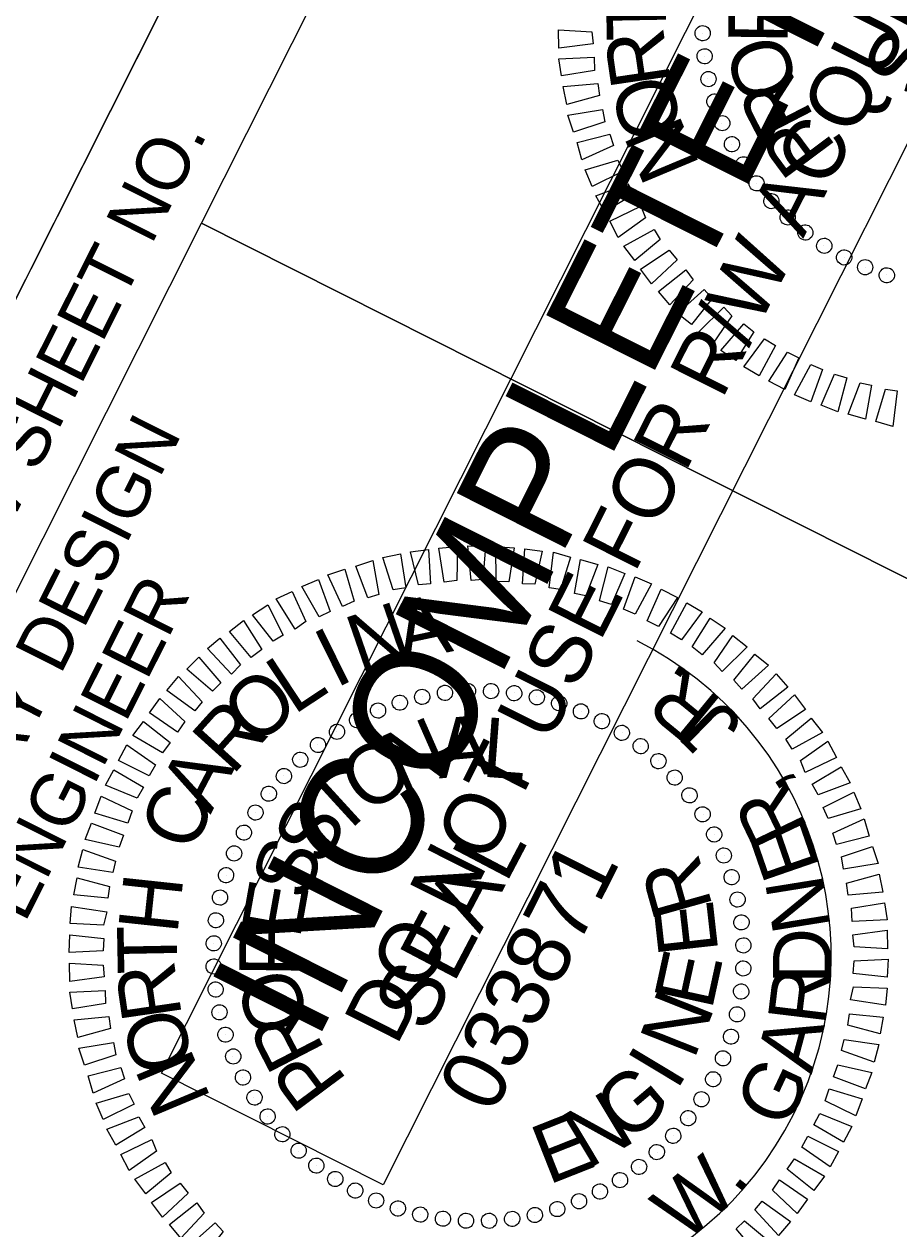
# Model space of a CAD drawing. Extents: x 2010322 to 2012069, y 441674 to 443687.
# Drawn here: x 2011069.6 to 2011152.3, y 443452.2 to 443566.2 of the extents above; entities that cross this region are included whole.
import ezdxf

# ---------------------------------------------------------------- set-up
doc = ezdxf.new("R2010")
doc.units = 0
for name, color, linetype in [('Scratch_Level_0', 7, 'Continuous'), ('Sheet Plan And Profile CELL', 7, 'Continuous'), ('Sheet Professional Seal CELL', 7, 'Continuous'), ('Sheet Profile Grid Minor CELL', 7, 'Continuous'), ('Sheet Sticker Incomplete CELL', 7, 'Continuous')]:
    doc.layers.add(name, color=color, linetype=linetype)

msp = doc.modelspace()

# ---------------------------------------------------------------- linework, layer by layer
at = {"layer": 'Scratch_Level_0'}
msp.add_arc((2011112.57, 443478.04), 33.36, 243.277, 63.277, dxfattribs=at)
at = {"layer": 'Sheet Plan And Profile CELL'}
for p, q in [((2011030.22, 443463.59), (2011120.17, 443642.28)), ((2011086.37, 443547.34), (2011186.81, 443496.77))]:
    msp.add_line(p, q, dxfattribs=at)
for points in [[(2011007.84, 443474.86), (2011097.8, 443653.54), (2011120.17, 443642.28), (2011030.22, 443463.59)], [(2011086.37, 443547.34), (2011131.34, 443636.65), (2011231.82, 443586.07), (2011186.86, 443496.75)], [(2011041.38, 443457.97), (2011086.37, 443547.34), (2011186.86, 443496.75), (2011141.87, 443407.38)]]:
    msp.add_lwpolyline(points, close=True, dxfattribs=at)
at = {"layer": 'Sheet Professional Seal CELL'}
for p, q in [((2011133.77, 443565.33), (2011133.77, 443565.33)), ((2011133.94, 443563.12), (2011133.94, 443563.12)), ((2011134.27, 443560.99), (2011134.27, 443560.99)), ((2011134.87, 443558.84), (2011134.87, 443558.84)), ((2011135.58, 443556.81), (2011135.58, 443556.81)), ((2011136.53, 443554.81), (2011136.53, 443554.81)), ((2011137.58, 443552.89), (2011137.58, 443552.89)), ((2011138.87, 443551.12), (2011138.87, 443551.12)), ((2011140.25, 443549.41), (2011140.25, 443549.41)), ((2011141.81, 443547.84), (2011141.81, 443547.84)), ((2011143.49, 443546.5), (2011143.49, 443546.5)), ((2011145.25, 443545.22), (2011145.25, 443545.22)), ((2011147.15, 443544.1), (2011147.15, 443544.1)), ((2011149.14, 443543.15), (2011149.14, 443543.15)), ((2011151.19, 443542.45), (2011151.19, 443542.45)), ((2011107.25, 443502.6), (2011107.25, 443502.6)), ((2011109.37, 443502.93), (2011109.37, 443502.93)), ((2011111.59, 443503.11), (2011111.59, 443503.11)), ((2011113.78, 443503.12), (2011113.78, 443503.12)), ((2011115.93, 443502.94), (2011115.93, 443502.94)), ((2011118.07, 443502.53), (2011118.07, 443502.53)), ((2011103.06, 443501.3), (2011103.06, 443501.3)), ((2011105.1, 443502.01), (2011105.1, 443502.01)), ((2011120.22, 443501.9), (2011120.22, 443501.9)), ((2011122.27, 443501.2), (2011122.27, 443501.2)), ((2011101.07, 443500.34), (2011101.07, 443500.34)), ((2011124.26, 443500.25), (2011124.26, 443500.25)), ((2011099.14, 443499.29), (2011099.14, 443499.29)), ((2011126.16, 443499.13), (2011126.16, 443499.13)), ((2011097.37, 443498), (2011097.37, 443498)), ((2011127.92, 443497.85), (2011127.92, 443497.85)), ((2011095.67, 443496.62), (2011095.67, 443496.62)), ((2011129.59, 443496.51), (2011129.59, 443496.51)), ((2011094.1, 443495.06), (2011094.1, 443495.06)), ((2011131.15, 443494.94), (2011131.15, 443494.94)), ((2011092.76, 443493.39), (2011092.76, 443493.39)), ((2011132.54, 443493.23), (2011132.54, 443493.23)), ((2011091.48, 443491.62), (2011091.48, 443491.62)), ((2011133.83, 443491.46), (2011133.83, 443491.46)), ((2011090.35, 443489.73), (2011090.35, 443489.73)), ((2011134.87, 443489.54), (2011134.87, 443489.54)), ((2011089.41, 443487.74), (2011089.41, 443487.74)), ((2011135.83, 443487.54), (2011135.83, 443487.54)), ((2011088.71, 443485.68), (2011088.71, 443485.68)), ((2011136.54, 443485.51), (2011136.54, 443485.51)), ((2011088.08, 443483.54), (2011088.08, 443483.54)), ((2011137.14, 443483.36), (2011137.14, 443483.36)), ((2011087.67, 443481.39), (2011087.67, 443481.39)), ((2011137.47, 443481.23), (2011137.47, 443481.23)), ((2011087.48, 443479.25), (2011087.48, 443479.25)), ((2011137.64, 443479.02), (2011137.64, 443479.02)), ((2011112.57, 443478.04), (2011112.57, 443478.04)), ((2011087.5, 443477.06), (2011087.5, 443477.06)), ((2011137.66, 443476.83), (2011137.66, 443476.83)), ((2011087.67, 443474.84), (2011087.67, 443474.84)), ((2011137.47, 443474.68), (2011137.47, 443474.68)), ((2011088, 443472.72), (2011088, 443472.72)), ((2011137.06, 443472.54), (2011137.06, 443472.54)), ((2011088.6, 443470.57), (2011088.6, 443470.57)), ((2011136.43, 443470.39), (2011136.43, 443470.39)), ((2011089.31, 443468.53), (2011089.31, 443468.53)), ((2011135.73, 443468.34), (2011135.73, 443468.34)), ((2011090.27, 443466.54), (2011090.27, 443466.54)), ((2011134.79, 443466.35), (2011134.79, 443466.35)), ((2011091.31, 443464.61), (2011091.31, 443464.61)), ((2011133.66, 443464.45), (2011133.66, 443464.45)), ((2011092.6, 443462.84), (2011092.6, 443462.84)), ((2011132.38, 443462.69), (2011132.38, 443462.69)), ((2011093.99, 443461.14), (2011093.99, 443461.14)), ((2011131.04, 443461.01), (2011131.04, 443461.01)), ((2011095.55, 443459.57), (2011095.55, 443459.57)), ((2011129.47, 443459.45), (2011129.47, 443459.45)), ((2011097.22, 443458.22), (2011097.22, 443458.22)), ((2011127.76, 443458.07), (2011127.76, 443458.07)), ((2011098.98, 443456.94), (2011098.98, 443456.94)), ((2011125.99, 443456.78), (2011125.99, 443456.78)), ((2011100.88, 443455.82), (2011100.88, 443455.82)), ((2011124.07, 443455.73), (2011124.07, 443455.73)), ((2011102.87, 443454.88), (2011102.87, 443454.88)), ((2011122.08, 443454.78), (2011122.08, 443454.78)), ((2011104.92, 443454.18), (2011104.92, 443454.18)), ((2011107.07, 443453.55), (2011107.07, 443453.55)), ((2011117.89, 443453.47), (2011117.89, 443453.47)), ((2011120.04, 443454.07), (2011120.04, 443454.07)), ((2011109.21, 443453.14), (2011109.21, 443453.14)), ((2011111.36, 443452.95), (2011111.36, 443452.95)), ((2011113.55, 443452.97), (2011113.55, 443452.97)), ((2011115.77, 443453.14), (2011115.77, 443453.14))]:
    msp.add_line(p, q, dxfattribs=at)
for points in [[(2011123.41, 443564.33), (2011120.17, 443563.89), (2011120.15, 443565.64), (2011123.3, 443565.45)], [(2011123.54, 443561.8), (2011120.43, 443561.3), (2011120.17, 443562.89), (2011123.5, 443563.06)], [(2011124.02, 443559.43), (2011120.91, 443558.59), (2011120.58, 443560.27), (2011123.87, 443560.57)], [(2011124.51, 443556.95), (2011121.56, 443555.97), (2011121.02, 443557.58), (2011124.31, 443558.11)], [(2011125.33, 443554.69), (2011122.35, 443553.33), (2011121.89, 443554.97), (2011124.98, 443555.76)], [(2011126.24, 443552.27), (2011123.33, 443550.83), (2011122.66, 443552.39), (2011125.75, 443553.3)], [(2011127.26, 443550.08), (2011124.53, 443548.43), (2011123.66, 443549.93), (2011126.71, 443551.08)], [(2011128.38, 443547.84), (2011125.78, 443546.01), (2011124.98, 443547.53), (2011127.93, 443548.96)], [(2011129.76, 443545.8), (2011127.36, 443543.82), (2011126.31, 443545.18), (2011129.18, 443546.76)], [(2011131.36, 443543.87), (2011128.94, 443541.62), (2011127.89, 443542.99), (2011130.6, 443544.81)], [(2011132.88, 443541.99), (2011130.68, 443539.62), (2011129.59, 443540.9), (2011132.19, 443542.95)], [(2011134.68, 443540.24), (2011132.71, 443537.76), (2011131.39, 443538.82), (2011133.92, 443541.07)], [(2011136.53, 443538.58), (2011134.78, 443535.99), (2011133.42, 443537.07), (2011135.78, 443539.41)], [(2011138.63, 443537.08), (2011136.93, 443534.35), (2011135.5, 443535.3), (2011137.67, 443537.84)], [(2011140.66, 443535.77), (2011139.11, 443532.92), (2011137.68, 443533.75), (2011139.64, 443536.4)], [(2011142.87, 443534.6), (2011141.55, 443531.63), (2011140.03, 443532.4), (2011141.8, 443535.14)], [(2011145.13, 443533.52), (2011144.02, 443530.44), (2011142.46, 443531.12), (2011144.01, 443533.98)], [(2011147.41, 443532.71), (2011146.57, 443529.5), (2011144.99, 443530.13), (2011146.25, 443533.07)], [(2011149.75, 443532.04), (2011149.19, 443528.8), (2011147.53, 443529.29), (2011148.68, 443532.24)], [(2011152.17, 443531.49), (2011151.76, 443528.12), (2011150.15, 443528.59), (2011151.07, 443531.65)], [(2011104.48, 443512.67), (2011103.51, 443515.74), (2011105.18, 443516.07), (2011105.69, 443512.85)], [(2011106.9, 443513.14), (2011106.12, 443516.27), (2011107.85, 443516.47), (2011108.02, 443513.25)], [(2011109.31, 443513.38), (2011108.81, 443516.6), (2011110.57, 443516.77), (2011110.52, 443513.55)], [(2011111.86, 443513.55), (2011111.56, 443516.84), (2011113.24, 443516.72), (2011112.98, 443513.66)], [(2011114.23, 443513.47), (2011114.22, 443516.78), (2011115.94, 443516.65), (2011115.44, 443513.43)], [(2011116.74, 443513.22), (2011116.95, 443516.53), (2011118.58, 443516.32), (2011117.9, 443513.2)], [(2011119.24, 443512.86), (2011119.65, 443516.23), (2011121.26, 443515.76), (2011120.34, 443512.7)], [(2011102.09, 443511.92), (2011100.95, 443514.9), (2011102.57, 443515.43), (2011103.14, 443512.23)], [(2011121.65, 443512.31), (2011122.22, 443515.55), (2011123.87, 443515.06), (2011122.73, 443512.11)], [(2011124, 443511.64), (2011124.84, 443514.85), (2011126.42, 443514.22), (2011125.16, 443511.28)], [(2011099.71, 443511.1), (2011098.31, 443514.1), (2011099.93, 443514.63), (2011100.81, 443511.61)], [(2011126.28, 443510.83), (2011127.38, 443513.91), (2011128.95, 443513.23), (2011127.39, 443510.37)], [(2011097.48, 443510.1), (2011095.85, 443512.99), (2011097.42, 443513.66), (2011098.53, 443510.63)], [(2011128.53, 443509.75), (2011129.86, 443512.72), (2011131.38, 443511.95), (2011129.61, 443509.21)], [(2011095.21, 443508.94), (2011093.41, 443511.81), (2011094.93, 443512.5), (2011096.24, 443509.66)], [(2011130.74, 443508.58), (2011132.29, 443511.43), (2011133.72, 443510.6), (2011131.77, 443507.95)], [(2011093.13, 443507.81), (2011091.19, 443510.3), (2011092.63, 443511.25), (2011094.09, 443508.39)], [(2011091.07, 443506.27), (2011089, 443508.71), (2011090.32, 443509.78), (2011092.06, 443507.01)], [(2011132.78, 443507.27), (2011134.48, 443510), (2011135.91, 443509.05), (2011133.73, 443506.51)], [(2011089.21, 443504.69), (2011086.91, 443507.13), (2011088.08, 443508.11), (2011090.04, 443505.56)], [(2011134.87, 443505.77), (2011136.62, 443508.36), (2011137.99, 443507.28), (2011135.63, 443504.94)], [(2011087.39, 443503.08), (2011084.96, 443505.15), (2011086.11, 443506.31), (2011088.18, 443503.86)], [(2011136.72, 443504.11), (2011138.7, 443506.59), (2011140.02, 443505.53), (2011137.48, 443503.28)], [(2011138.53, 443502.36), (2011140.73, 443504.73), (2011141.82, 443503.45), (2011139.22, 443501.4)], [(2011085.73, 443501.23), (2011083.06, 443503.14), (2011084.18, 443504.48), (2011086.43, 443502.06)], [(2011084.1, 443499.2), (2011081.44, 443501.04), (2011082.41, 443502.4), (2011084.77, 443500.21)], [(2011140.05, 443500.48), (2011142.47, 443502.73), (2011143.51, 443501.36), (2011140.8, 443499.54)], [(2011082.66, 443497.24), (2011079.85, 443498.88), (2011080.86, 443500.22), (2011083.38, 443498.22)], [(2011141.65, 443498.55), (2011144.05, 443500.54), (2011145.1, 443499.17), (2011142.23, 443497.59)], [(2011081.4, 443495.07), (2011078.5, 443496.53), (2011079.29, 443497.99), (2011081.99, 443496.12)], [(2011143.03, 443496.51), (2011145.63, 443498.34), (2011146.43, 443496.82), (2011143.48, 443495.39)], [(2011080.28, 443492.95), (2011077.26, 443494.19), (2011078.05, 443495.64), (2011080.86, 443494)], [(2011144.14, 443494.27), (2011146.88, 443495.92), (2011147.74, 443494.42), (2011144.7, 443493.27)], [(2011145.17, 443492.08), (2011148.08, 443493.53), (2011148.74, 443491.96), (2011145.66, 443491.05)], [(2011079.38, 443490.61), (2011076.27, 443491.55), (2011076.86, 443493.16), (2011079.78, 443491.75)], [(2011146.08, 443489.66), (2011149.05, 443491.02), (2011149.52, 443489.38), (2011146.43, 443488.59)], [(2011078.57, 443488.33), (2011075.35, 443489.05), (2011075.96, 443490.59), (2011078.97, 443489.47)], [(2011077.98, 443485.94), (2011074.69, 443486.42), (2011075.14, 443488.09), (2011078.23, 443486.99)], [(2011146.9, 443487.4), (2011149.85, 443488.38), (2011150.38, 443486.77), (2011147.1, 443486.24)], [(2011077.48, 443483.5), (2011074.28, 443483.82), (2011074.58, 443485.41), (2011077.64, 443484.6)], [(2011147.38, 443484.92), (2011150.49, 443485.76), (2011150.82, 443484.08), (2011147.54, 443483.78)], [(2011147.87, 443482.55), (2011150.98, 443483.05), (2011151.24, 443481.46), (2011147.91, 443481.29)], [(2011077.09, 443480.95), (2011073.92, 443481.1), (2011074.06, 443482.71), (2011077.39, 443482.2)], [(2011077.04, 443478.52), (2011073.82, 443478.35), (2011073.89, 443480.04), (2011077.13, 443479.7)], [(2011147.99, 443480.02), (2011151.24, 443480.46), (2011151.26, 443478.71), (2011148.1, 443478.9)], [(2011077.15, 443476.06), (2011073.9, 443475.62), (2011073.88, 443477.36), (2011077.04, 443477.17)], [(2011148.1, 443477.56), (2011151.32, 443477.73), (2011151.25, 443476.03), (2011148.01, 443476.37)], [(2011148.05, 443475.12), (2011151.22, 443474.98), (2011151.08, 443473.37), (2011147.75, 443473.87)], [(2011077.27, 443473.53), (2011074.16, 443473.02), (2011073.9, 443474.61), (2011077.23, 443474.78)], [(2011077.76, 443471.16), (2011074.65, 443470.32), (2011074.32, 443471.99), (2011077.6, 443472.3)], [(2011147.66, 443472.57), (2011150.86, 443472.25), (2011150.56, 443470.67), (2011147.5, 443471.48)], [(2011078.24, 443468.67), (2011075.29, 443467.7), (2011074.76, 443469.31), (2011078.04, 443469.84)], [(2011147.16, 443470.14), (2011150.45, 443469.66), (2011150, 443467.98), (2011146.91, 443469.09)], [(2011079.06, 443466.41), (2011076.09, 443465.06), (2011075.62, 443466.69), (2011078.71, 443467.49)], [(2011146.57, 443467.75), (2011149.79, 443467.02), (2011149.18, 443465.48), (2011146.17, 443466.61)], [(2011079.97, 443464), (2011077.06, 443462.55), (2011076.4, 443464.12), (2011079.48, 443465.03)], [(2011145.76, 443465.47), (2011148.87, 443464.52), (2011148.28, 443462.91), (2011145.36, 443464.33)], [(2011081, 443461.8), (2011078.26, 443460.15), (2011077.4, 443461.65), (2011080.44, 443462.81)], [(2011144.86, 443463.12), (2011147.88, 443461.89), (2011147.09, 443460.43), (2011144.28, 443462.07)], [(2011082.11, 443459.56), (2011079.51, 443457.74), (2011078.71, 443459.26), (2011081.66, 443460.68)], [(2011143.74, 443461), (2011146.64, 443459.54), (2011145.85, 443458.09), (2011143.15, 443459.95)], [(2011083.49, 443457.52), (2011081.09, 443455.54), (2011080.04, 443456.91), (2011082.91, 443458.49)], [(2011142.48, 443458.84), (2011145.29, 443457.2), (2011144.28, 443455.86), (2011141.76, 443457.85)], [(2011141.04, 443456.87), (2011143.7, 443455.03), (2011142.73, 443453.67), (2011140.37, 443455.87)], [(2011085.09, 443455.6), (2011082.67, 443453.34), (2011081.63, 443454.71), (2011084.34, 443456.54)], [(2011086.61, 443453.71), (2011084.41, 443451.35), (2011083.32, 443452.63), (2011085.92, 443454.68)], [(2011139.41, 443454.84), (2011142.08, 443452.93), (2011140.96, 443451.6), (2011138.71, 443454.02)], [(2011088.42, 443451.96), (2011086.44, 443449.49), (2011085.12, 443450.54), (2011087.66, 443452.79)], [(2011137.75, 443452.99), (2011140.18, 443450.93), (2011139.03, 443449.77), (2011136.96, 443452.21)]]:
    msp.add_lwpolyline(points, close=True, dxfattribs=at)
for centre, major_axis in [((2011133.78, 443565.32), (-0.719, -0.029)), ((2011133.96, 443563.14), (-0.714, -0.091)), ((2011134.33, 443560.98), (-0.704, -0.153)), ((2011134.89, 443558.86), (-0.688, -0.214)), ((2011135.63, 443556.81), (-0.666, -0.273)), ((2011136.55, 443554.82), (-0.64, -0.33)), ((2011137.63, 443552.92), (-0.609, -0.384)), ((2011138.88, 443551.12), (-0.573, -0.436)), ((2011140.28, 443549.44), (-0.533, -0.484)), ((2011141.82, 443547.89), (-0.488, -0.529)), ((2011143.49, 443546.47), (-0.441, -0.57)), ((2011145.28, 443545.21), (-0.389, -0.606)), ((2011147.17, 443544.11), (-0.335, -0.637)), ((2011149.15, 443543.18), (-0.278, -0.664)), ((2011151.2, 443542.42), (-0.219, -0.686)), ((2011109.39, 443502.92), (-0.091, 0.714)), ((2011111.57, 443503.1), (-0.029, 0.719)), ((2011113.76, 443503.09), (0.034, 0.719)), ((2011115.94, 443502.89), (0.097, 0.713)), ((2011105.12, 443501.99), (-0.214, 0.688)), ((2011107.24, 443502.54), (-0.153, 0.704)), ((2011118.09, 443502.5), (0.159, 0.702)), ((2011120.2, 443501.93), (0.219, 0.686)), ((2011103.06, 443501.25), (-0.273, 0.666)), ((2011122.26, 443501.17), (0.278, 0.664)), ((2011099.18, 443499.24), (-0.384, 0.609)), ((2011101.08, 443500.33), (-0.33, 0.64)), ((2011124.24, 443500.24), (0.335, 0.637)), ((2011126.13, 443499.14), (0.389, 0.606)), ((2011097.38, 443497.99), (-0.436, 0.573)), ((2011127.91, 443497.88), (0.441, 0.57)), ((2011095.7, 443496.59), (-0.484, 0.533)), ((2011129.59, 443496.46), (0.488, 0.529)), ((2011094.15, 443495.05), (-0.529, 0.488)), ((2011131.13, 443494.91), (0.533, 0.484)), ((2011092.73, 443493.38), (-0.57, 0.441)), ((2011132.53, 443493.23), (0.573, 0.436)), ((2011091.47, 443491.6), (-0.606, 0.389)), ((2011133.77, 443491.43), (0.609, 0.384)), ((2011090.37, 443489.7), (-0.637, 0.335)), ((2011134.86, 443489.53), (0.64, 0.33)), ((2011089.44, 443487.73), (-0.664, 0.278)), ((2011135.78, 443487.54), (0.666, 0.273)), ((2011088.68, 443485.67), (-0.686, 0.219)), ((2011136.52, 443485.49), (0.688, 0.214)), ((2011088.11, 443483.56), (-0.702, 0.159)), ((2011137.08, 443483.37), (0.704, 0.153)), ((2011087.72, 443481.41), (-0.713, 0.097)), ((2011137.45, 443481.21), (0.714, 0.091)), ((2011087.52, 443479.23), (-0.719, 0.034)), ((2011137.63, 443479.03), (0.719, 0.029)), ((2011087.51, 443477.04), (-0.719, -0.029)), ((2011137.62, 443476.85), (0.719, -0.034)), ((2011087.69, 443474.86), (-0.714, -0.091)), ((2011137.42, 443474.67), (0.713, -0.097)), ((2011088.06, 443472.7), (-0.704, -0.153)), ((2011137.03, 443472.51), (0.702, -0.159)), ((2011088.62, 443470.59), (-0.688, -0.214)), ((2011136.46, 443470.4), (0.686, -0.219)), ((2011089.36, 443468.53), (-0.666, -0.273)), ((2011135.7, 443468.35), (0.664, -0.278)), ((2011090.28, 443466.54), (-0.64, -0.33)), ((2011134.77, 443466.37), (0.637, -0.335)), ((2011091.37, 443464.64), (-0.609, -0.384)), ((2011133.67, 443464.48), (0.606, -0.389)), ((2011092.61, 443462.85), (-0.573, -0.436)), ((2011132.41, 443462.69), (0.57, -0.441)), ((2011094.01, 443461.17), (-0.533, -0.484)), ((2011130.99, 443461.02), (0.529, -0.488)), ((2011095.55, 443459.61), (-0.488, -0.529)), ((2011129.44, 443459.48), (0.484, -0.533)), ((2011097.22, 443458.2), (-0.441, -0.57)), ((2011127.76, 443458.08), (0.436, -0.573)), ((2011099.01, 443456.94), (-0.389, -0.606)), ((2011125.96, 443456.83), (0.384, -0.609)), ((2011100.9, 443455.84), (-0.335, -0.637)), ((2011102.88, 443454.9), (-0.278, -0.664)), ((2011122.08, 443454.83), (0.273, -0.666)), ((2011124.06, 443455.75), (0.33, -0.64)), ((2011104.94, 443454.15), (-0.219, -0.686)), ((2011120.02, 443454.09), (0.214, -0.688)), ((2011107.05, 443453.57), (-0.159, -0.702)), ((2011109.2, 443453.18), (-0.097, -0.713)), ((2011111.38, 443452.99), (-0.034, -0.719)), ((2011113.57, 443452.98), (0.029, -0.719)), ((2011115.75, 443453.16), (0.091, -0.714)), ((2011117.9, 443453.53), (0.153, -0.704))]:
    msp.add_ellipse(centre, major_axis=major_axis, ratio=0.999708, dxfattribs=at)
at = {"layer": 'Sheet Sticker Incomplete CELL'}
msp.add_lwpolyline([(2011103.56, 443456.39), (2011082.57, 443466.96), (2011148.67, 443598.26), (2011169.66, 443587.69)], close=True, dxfattribs=at)

# ---------------------------------------------------------------- texts
at = {"layer": 'Sheet Plan And Profile CELL'}
for s, height, p in [('R/W SHEET NO.', 5.0001, (2011064.07, 443510.37)), ('ROADWAY DESIGN', 5.0001, (2011056.63, 443472.02)), ('ENGINEER', 5, (2011069.64, 443481.08))]:
    msp.add_text(s, height=height, rotation=63.277, dxfattribs=at).set_placement(p)
at = {"layer": 'Sheet Professional Seal CELL'}
for s, height, rotation, p in [('SEAL', 5.998, 62.277, (2011153.96, 443558.86)), ('T', 5.64, 91.0968, (2011130.35, 443564.65)), ('F', 5.64, 89.2441, (2011141.82, 443564.3)), ('R', 5.64, 98.2975, (2011130.78, 443560.62)), ('O', 5.64, 107.9583, (2011142.97, 443560.03)), ('R', 5.64, 117.3167, (2011144.37, 443557.36)), ('O', 5.64, 105.4988, (2011132, 443556.15)), ('N', 5.64, 112.7005, (2011133.55, 443552.79)), ('P', 5.64, 126.6759, (2011146.51, 443554.5)), ('N', 5.64, 19.0959, (2011101.4, 443504.54)), ('A', 5.64, 11.8942, (2011105.36, 443505.85)), ('I', 5.64, 26.2972, (2011099.04, 443503.32)), ('L', 5.64, 33.4979, (2011095.08, 443500.78)), ('O', 5.64, 40.6982, (2011091.45, 443497.68)), ('R', 5.64, 47.8981, (2011089.27, 443495.03)), ('N', 5.64, 23.7536, (2011105.21, 443493.44)), ('A', 5.64, 5.0373, (2011108.81, 443494.82)), ('L', 5.64, 355.6779, (2011112.77, 443495.01)), ('O', 5.64, 33.1105, (2011101.92, 443491.35)), ('A', 5.64, 62.2974, (2011087.2, 443491.37)), ('I', 5.64, 42.4666, (2011100.39, 443489.88)), ('C', 5.64, 69.4969, (2011085.7, 443487.7)), ('S', 5.64, 61.1774, (2011097.83, 443486.35)), ('S', 5.64, 70.5326, (2011096.26, 443483.11)), ('SEAL', 5.998, 62.277, (2011107.7, 443470.58)), ('R', 5.64, 105.7584, (2011134.76, 443482.65)), ('H', 5.64, 83.8965, (2011084.07, 443480.02)), ('E', 5.64, 79.8881, (2011095.65, 443479.56)), ('E', 5.64, 96.4011, (2011135.27, 443478.42)), ('T', 5.64, 91.0968, (2011084.08, 443476.37)), ('F', 5.64, 89.2441, (2011095.55, 443476.03)), ('E', 5.64, 77.6888, (2011134.63, 443472.81)), ('R', 5.64, 98.2975, (2011084.51, 443472.35)), ('O', 5.64, 107.9583, (2011096.7, 443471.75)), ('N', 5.64, 68.3334, (2011132.94, 443468.12)), ('R', 5.64, 117.3167, (2011098.1, 443469.09)), ('O', 5.64, 105.4988, (2011085.73, 443467.87)), ('I', 5.64, 58.9782, (2011131.3, 443465.2)), ('N', 5.64, 112.7005, (2011087.29, 443464.51)), ('P', 5.64, 126.6759, (2011100.24, 443466.22)), ('G', 5.64, 40.2673, (2011126.65, 443460.2)), ('N', 5.64, 30.911, (2011122.93, 443457.82)), ('E', 5.64, 21.5539, (2011119.17, 443456.35))]:
    msp.add_text(s, height=height, rotation=rotation, dxfattribs=at).set_placement(p)
at = {"layer": 'Sheet Profile Grid Minor CELL'}
for s, height, rotation, p in [('R', 5.5, 140.6311, (2011135.79, 443502.14)), ('.', 5.5, 147.5575, (2011132.72, 443504.77)), ('J', 5.5, 135.7625, (2011137.75, 443500.08)), ('R', 5.5, 115.6558, (2011143.8, 443490.08)), (',', 5.5, 122.5823, (2011142.12, 443493.76)), ('E', 5.5, 109.0728, (2011144.97, 443486.42)), ('033871', 5.998, 63.277, (2011113.92, 443462.92)), ('N', 5.5, 99.1411, (2011145.93, 443480.71)), ('D', 5.5, 89.9965, (2011145.93, 443475.37)), ('R', 5.5, 83.0701, (2011145.37, 443471.37)), ('A', 5.5, 74.8843, (2011144.09, 443466.77)), ('G', 5.5, 64.9525, (2011141.67, 443461.5)), ('W', 5.5, 40.1662, (2011132.06, 443450.82)), ('.', 5.5, 51.7723, (2011137.13, 443455.3))]:
    msp.add_text(s, height=height, rotation=rotation, dxfattribs=at).set_placement(p)
at = {"layer": 'Sheet Sticker Incomplete CELL'}
for s, height, p in [('INCOMPLETE PLANS', 11.52, (2011097.14, 443469.65)), ('DO NOT USE FOR R/W ACQUISITION', 5.76, (2011104.81, 443469.42))]:
    msp.add_text(s, height=height, rotation=63.277, dxfattribs=at).set_placement(p)

doc.saveas('drawing.dxf')
